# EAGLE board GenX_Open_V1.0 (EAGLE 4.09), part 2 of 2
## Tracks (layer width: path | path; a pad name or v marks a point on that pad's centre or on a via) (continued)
N$29  (via drill 0.43) (continued)
  Top 0.406: 31.55,98.37 v31.77,99.24 | 41.44,102.68 D1.C | v39.12,101.7 39.12,100.97 38.63,100.97 38.51,100.84 38.5,100.85 L3.1 37.55,100.85 36.85,100.15 36.63,100.1 36.83,100.1
  Bottom 0.203: 36.3,100.05 v36.73,100.1
  Bottom 0.406: v31.77,99.24 32.59,100.05 36.3,100.05 | v41.4,102.64 40.06,102.64 v39.12,101.7
N$30
  Top 0.203: R50.1 9.42,105.39 12.83,105.39 13.16,105.69 J15.1
N$31
  Top 0.203: R43.2 26.01,25.38 26.01,24.05 LD2.P$1
N$32
  Top 0.61: J6B.2 32.84,6.15 32.84,6.27
  Top 1.016: U9.5 U9.6 U9.7 U9.8 31.27,11.84 32.82,10.29 32.84,6.27
  Bottom 1.016: J6.4 32.26,9.6 32.79,9.07 32.84,6.15 32.82,6.15 32.84,6.12 J6B.2
N$33
  Top 0.203: LD3.P$1 21.07,23.76 21.27,23.96 R42.2
N$34
  Top 0.203: U8.8 23.88,14.28 | 23.16,14.28 U8.7 22.84,14.3 | 21.79,14.3 U8.6 21.74,14.33 | 20.55,14.33 U8.5
  Top 0.61: 24.46,12.17 24.21,12.42 | 26.19,2.9 26.16,2.92 J4.4
  Top 1.016: 23.88,14.28 23.16,14.28 | 22.84,14.3 21.79,14.3 | 21.74,14.33 20.55,14.33 | 24.21,12.42 U8.8 | 24.46,12.17 27.58,12.14 28.07,11.61 28.07,3.25 27.71,2.9 26.19,2.9
N$35
  Top 0.203: R40.2 25.83,28.52 25.83,28.17 24.51,26.85 24.51,21.21 24.33,21.03 20.5,21.03 20.4,20.93 20.4,19.84 20.42,19.81 20.4,19.79 U8.4
N$36  (via drill 0.43)
  Top 0.203: v23.47,21.87 23.47,25.88 23.32,26.04 v22.53,26.04 | 21.16,28.65 R41.2 | v22.35,28.65 21.16,28.65 | 21.16,28.65 21.11,28.6 | U9.4 v26.24,19.86
  Bottom 0.203: v22.53,26.04 22.53,27.25 22.38,27.41 22.38,28.63 v22.35,28.65 | v23.47,21.87 26.06,21.84 26.16,21.74 26.16,19.94 v26.24,19.86
N$37
  Top 0.406: J12.1 11.81,45.85 11.35,46.31 L1.2
N$38  (via drill 0.43)
  Top 0.203: v29.9,57.89 30.35,58.24 30.35,62.87 29.59,63.7 29.59,64.39 29.36,64.64 28.83,64.64 U7.29 | v32,57.35 32,56.08 31.24,55.32 31.24,54.08 32,53.31 32,49.94 30.61,48.54 30.61,40.16 v31.01,39.78 | C61.1 18.44,20.8 18.69,21.06 19.63,21.06 20.34,21.77 22.35,21.77 22.61,22.02 22.61,23.7 v22.55,23.85
  Bottom 0.203: v29.9,57.89 30.18,57.89 30.63,57.43 31.55,57.43 31.75,57.23 31.77,57.35 v32,57.35 | v31.01,39.78 30.89,39.57 25.81,39.57 25.38,39.14 25.38,38.94 25.43,29.54 25.43,29.39 25.22,29.18 23.75,29.18 23.14,28.07 23.14,27.08 23.5,26.7 23.5,25.45 23.29,25.25 23.29,24.71 22.5,23.93 v22.55,23.85
N$39
  Top 0.254: 35.92,105.49 36.14,105.49 | 35.18,106.22 34.67,106.22 34.44,106.45 | C63.1 32.69,106.7 32.94,106.45
  Top 0.305: 35.18,106.22 35.92,105.49 | 32.94,106.45 34.44,106.45
  Top 0.406: D3.A 38.45,105.16 38.48,105.13 L3.2 36.3,105.05 36.14,105.49 R36.2
N$40
  Top 0.203: R31.2 8.94,18.21 9.98,17.17 10.34,17.17 10.41,17.09 10.46,17.14 U12.2
N$41  (via drill 0.43)
  Top 0.203: R57.1 16.76,40.53 15.75,40.16 15.14,39.34 v14.53,39.34 | U11.1 17.04,35.26 16.23,35.23 15.47,35.23 15.32,35.31 15.32,35.36 15.14,35.51 14.25,35.51 | J9.2 3.91,35.33 4.09,35.51 9.02,35.51 9.35,35.84 12.17,35.84 12.5,35.51 14.25,35.51 | v14.35,36.14 14.35,35.53 14.25,35.51
  Bottom 0.203: v14.53,39.34 14.53,38.51 14.12,38.2 14.12,36.42 v14.35,36.14
N$42
  Top 0.406: U12.6 U12.5 16.1,8.41 15.67,7.98 8.1,7.98 7.82,7.7 J8.3
N$43
  Top 0.406: U12.8 U12.7 14.22,17.14 14.07,16.99 14.07,10.13 13.59,9.63 6.73,9.63 5.28,8.48 J8.4
N$44
  Top 0.203: R48.1 22.48,99.31 22.02,99.62 22.02,103.73 21.89,103.86 20.57,103.86 20.4,104.04 J16.1
N$45
  Top 0.61: D4.C 40.78,10.68 40.16,10.06 38.3,10.06 37.8,9.55 37.8,6.27 37.95,6.12 J6B.1 | J11.1 48.9,6.02 48.95,5.97 48.9,5.92
  Top 1.016: J6B.1 37.92,3.3 38.51,2.72 48.54,2.72 48.9,3.07 48.9,5.92 | J11.1 52.7,6.12 52.98,5.84 52.98,5.08 53.54,4.52 J6C.2
  Bottom 0.61: 37.72,2.9 37.92,3.1 | 37.92,5.44 37.87,5.49 37.87,6.12 J6B.1
  Bottom 1.016: J6.3 23.44,5.56 23.77,5.23 30.12,5.23 30.23,5.13 30.23,3.63 30.96,2.9 37.72,2.9 | 37.92,3.1 37.92,5.44
N$47
  Top 0.203: R46.1 28.32,97.51 27.91,97.81 27.91,104.27 27.46,104.52 J17.1
N$48  (via drill 0.43)
  Top 0.203: v12.98,62.26 12.98,62.31 15.77,62.31 U7.8 | v9.2,62 9.12,62 C41.1 9.37,62.31 9.37,63.32 Q1.1
  Bottom 0.203: v12.98,62.26 12.72,62 v9.2,62
N$49  (via drill 0.43)
  Top 0.203: U11.3 15.28,37.81 v15.14,37.54 | v8.87,20.34 8.18,19.68 2.34,19.68 2.08,19.53 2.08,18.49 2.06,18.47 2.08,18.45 R23.1 | v13.79,29.62 10.03,29.62 v10.01,29.64
  Bottom 0.203: v15.14,37.54 15.14,32.77 13.79,31.24 v13.79,29.62 | v10.01,29.64 10.01,28.6 9.27,27.86 9.12,27.69 8.69,27.25 8.69,26.16 9.32,25.53 9.32,21.01 8.87,20.55 v8.87,20.34
N$51  (via drill 0.43)
  Top 0.203: v12.55,37.74 U11.6 | v11.73,25.68 11.73,23.95 v11.68,23.9 | v11.71,19.46 11.02,19.46 10.9,19.25 6.71,19.25 6.5,19.1 6.5,18.39 6.52,18.37 6.53,18.19 6.52,18.19 R31.1
  Bottom 0.203: v12.55,37.74 13.31,37.72 13.51,37.52 13.51,32.11 13.18,31.83 11.86,31.83 11.63,31.6 11.66,25.76 v11.73,25.68 | v11.68,23.9 11.68,19.43 v11.71,19.46
N$55  (via drill 0.43)
  Top 0.203: R65.2 20.93,85.65 v20.88,85.37 | R45.2 24.44,83.89 24.38,83.95 24.43,84 v24.71,85.75 | R38.2 26.98,84.89 26.95,85.42 | 26.95,85.42 26.95,86.56 26.82,86.79 26.54,87.1 U13.1 | v26.29,84.71 26.95,84.71 26.95,85.42
  Bottom 0.203: v20.88,85.37 24.28,85.37 v24.71,85.75 25.88,85.22 v26.29,84.71
RESET  (via drill 0.43)
  Top 0.203: v14.2,65.35 15.77,65.35 U7.4 | v8.08,65.84 7.95,66.47 v7.95,72.08 7.95,72.92 7.72,73.15 7.72,79.12 8.05,79.45 S1.2 12.47,79.45 12.62,79.22 12.62,77.95 | 12.62,77.95 12.62,75.11 12.88,74.85 12.88,73.74 R5.1 | 12.62,77.95 13.39,77.95 C43.1
  Bottom 0.203: v14.2,65.35 13.31,65.81 v8.08,65.84 | v7.95,72.08 7.29,72.06 J3.5 | S1.1 5.11,79.43 8.51,79.43 S1.2
RESET_A  (via drill 0.43)
  Top 0.203: U4.12 40.1,25.92 39.42,26.57 37.85,26.57 v37.67,26.39 | U3.12 40.02,46.36 38.94,47.3 36.85,47.3 v36.27,47.42 | U1.12 39.92,87.41 39.24,88.06 v36.93,88.06 | U2.12 39.49,66.89 38.81,67.54 35.59,67.54 v35.51,67.46 | v31.8,67.51 31.8,67.54 31.67,67.74 31.47,68.17 31.47,80.92 31.19,81.23 v31.19,88.06 | v23.9,45.64 23.6,46.05 23.6,51.97 22.96,52.55 22.96,55.47 22.71,55.7 20.95,55.7 20.7,55.91 20.7,57.33 U7.15 20.75,58.75 20.75,58.98 19.53,60.38 19.53,61.67 19.74,61.87 23.57,62.2 23.8,62.41 23.8,65.76 v24.13,66.24 | v32.44,47.02 31.34,47.02 31.17,46.81 31.17,41.15 31.98,40.18 31.98,39.01 33.17,37.8 33.17,31.09 32.13,30.4 32.13,27.23 32.41,26.95 v32.41,26.26
  Bottom 0.203: 32.51,47.02 v32.44,47.02 31.98,47.22 30.3,47.22 30.05,46.91 24.05,46.91 23.9,46.81 v23.9,45.64 | 32.51,47.02 32.03,47.27 | v32.41,26.26 32.18,26.44 32.66,26.39 v37.67,26.39 | 32.51,47.02 32.51,47.04 32.74,47.45 v36.27,47.42 | v35.51,67.46 31.95,67.46 31.88,67.54 31.85,67.51 v31.8,67.51 31.85,67.46 31.45,67.46 31.39,67.41 30.38,67.41 29.21,66.24 v24.13,66.24 | v31.19,88.06 31.57,88.01 33.86,87.99 34.14,87.71 36.09,87.71 36.4,88.01 36.83,88.01 v36.93,88.06
RXD0  (via drill 0.43)
  Top 0.203: v16.59,53.57 16.59,52.43 U6.9 | v10.72,53.34 10.08,52.81 9.37,52.81 R26.2 | v13.89,61.44 15.77,61.44 U7.9
  Bottom 0.203: v16.59,53.57 16.38,53.59 11.4,53.59 11.28,53.34 v10.72,53.34 10.29,53.67 9.42,53.67 8,54.69 5.21,54.69 5.03,54.94 5.03,57.99 5.18,58.22 6.3,58.22 6.53,58.45 6.53,60.68 6.73,60.88 10.77,60.88 11.3,61.42 13.31,61.42 v13.89,61.44
RXD1  (via drill 0.43)
  Top 0.203: v15.77,52.65 15.72,52.7 15.72,52.88 15.54,52.96 15.54,54.61 14.63,55.83 14.63,58.47 15.72,59.31 15.82,59.61 15.95,59.77 U7.11 | J2.3 9.68,26.62 v9.7,26.64
  Bottom 0.203: v15.77,52.65 14.99,51.94 14.99,47.9 15.75,47.22 15.75,44.93 16.13,44.55 17.42,44.55 17.68,44.22 17.7,35.23 16.97,34.62 16.97,33.05 17.55,32.51 17.55,30.89 17.91,30.53 17.91,28.57 18.14,28.35 20.3,28.35 20.37,28.32 20.47,28.22 20.47,26.52 20.24,26.26 16.97,26.26 16.28,25.6 16.28,25.3 16.1,25.15 13.31,25.15 13.23,25.09 J1.3 12.52,25.09 12.27,24.84 10.21,24.84 9.98,25.12 9.98,26.62 9.96,26.64 v9.7,26.64
SCK  (via drill 0.43)
  Top 0.203: v5.82,95.99 15.72,95.99 J7.5 | v5.71,80.24 6.02,79.68 6.02,71.4 5.84,71.12 5.84,69.52 | v14.15,69.47 14.15,66.37 14.3,66.22 15.77,66.22 U7.3 | v5.31,60.66 5.41,60.58 5.18,60.35 5.18,58.52 4.85,58.17 4.42,58.01 4.32,57.86 R10.1 | 5.84,69.52 5.84,67.94 6.1,67.67 6.1,64.31 6.07,64.19 v5.74,64.03 | 5.84,69.52 J3.3
  Bottom 0.203: v5.82,95.99 5.71,95.48 5.71,85.52 5.41,85.22 5.41,81.1 5.71,80.8 v5.71,80.24 | v14.15,69.47 13.95,69.52 J3.3 | v5.31,60.66 5.41,60.78 5.74,61.24 v5.74,64.03
SCL  (via drill 0.43)
  Top 0.203: U11.7 12.45,36.5 v12.7,36.47 | v5.69,45.57 5.69,48.79 5.84,48.95 J10.3 | U7.19 23.9,58.98 23.44,59.44 22.63,59.49 v21.36,60.43 | v16.74,58.34 16.74,58.24 17.04,57.78 v17.04,55.24 | v6.68,56.13 5.49,56.13 5.23,56.39 5.23,57.78 5.66,58.22 5.66,59.72 6.25,60.6 6.25,61.19 5.99,61.49 4.75,61.49 4.24,61.82 3.63,61.82 3.63,61.8 J10B.3 | R61.1 33.88,58.14 v32.99,58.14
  Bottom 0.203: v12.7,36.47 3.99,36.47 3.79,36.63 3.79,45.34 3.94,45.57 v5.69,45.57 | J10B.3 4.38,61.81 4.47,61.59 4.47,54.41 4.83,54 6.45,54 6.63,53.82 6.63,49.15 6.93,48.84 | v16.74,58.34 17.83,58.34 17.93,58.42 17.93,60.68 18.14,60.88 20.55,60.88 20.95,60.43 v21.36,60.43 21.36,60.45 21.39,60.48 21.36,60.5 21.36,60.55 22.28,61.87 24.69,61.87 25.81,60.38 25.81,58.95 26.01,58.8 30.48,58.8 30.99,58.14 v32.99,58.14 | v17.04,55.24 16.69,55.32 16.08,54.74 9.68,54.74 8.18,56.06 6.76,56.06 v6.68,56.13 | J10.3 6.93,48.84 | 6.93,48.84 6.96,48.84 6.99,48.82
SDA  (via drill 0.43)
  Top 0.203: U11.5 11.5,39.09 v11.56,39.78 | U7.20 24.7,59.32 24.38,59.64 23.93,59.64 23.01,60.55 22.68,60.55 v22.66,60.63 | R60.1 33.07,56.11 v32.66,55.63 | v11.48,55.6 11.48,54.69 11.76,54.56 11.76,51.92 v11.3,51.56 | v15.8,55.6 15.49,56.26 v15.49,58.04
  Bottom 0.203: v11.56,39.78 11.56,40.72 11.35,40.95 8.36,40.95 8.18,41.17 8.18,46.2 7.92,46.53 4.52,46.53 4.37,46.71 4.37,48.44 | J10B.2 3.52,60.56 3.5,60.58 3.02,60.58 2.52,60.07 2.52,58.24 2.69,58.06 3.45,58.06 3.76,57.76 3.76,54.28 4.37,53.67 J10.2 4.37,48.49 4.39,48.46 4.37,48.44 | v32.66,55.63 31.7,55.63 30.63,56.77 29.87,56.77 28.78,57.56 28.78,58.04 28.55,58.22 25.63,58.22 25.35,58.45 25.35,60.2 24.49,61.42 22.99,61.42 22.63,60.76 22.63,60.6 | 22.63,60.6 v22.66,60.63 | 22.63,60.6 22.63,60.1 22.3,59.59 20.75,59.61 19.58,60.35 18.62,60.38 18.36,60.12 18.36,57.58 18.26,57.4 16.92,57.4 15.98,57.68 v15.49,58.04 | v11.48,55.6 15.72,55.6 15.95,55.73 v15.8,55.6 | v11.3,51.56 8.33,51.56 8.13,51.36 8.1,48.72 7.29,47.62 4.42,47.62 4.39,47.55 4.39,48.41 4.37,48.44
SLEEP  (via drill 0.43)
  Top 0.203: U3.14 41.2,45.36 v40.89,44.76 v40.89,40.62 | U4.14 40.64,24.92 40.08,24.46 | 40.08,24.46 39.65,24.11 R29.1 | U1.14 40.46,86.41 40.18,86.18 40.18,81.64 40.21,81.64 40.23,81.61 40.18,81.56 v40.18,77.8 | U2.14 41.2,65.89 v40.87,65.25 40.62,64.75 40.62,60.55 40.36,60.3 40.36,57.07 40.16,56.87 38.63,56.87 38.46,56.69 38.46,53.87 37.74,53.16 v37.74,50.49 | 40.08,24.46 39.93,24.46 v39.93,24.41 | v38.1,30.07 37.64,30.2 37.64,33.07 38.46,33.58 38.46,37.26 38.58,37.36 v39.98,37.36
  Bottom 0.203: 40.89,40.59 v40.89,40.62 40.89,38.2 v39.98,37.36 | v39.93,24.41 39.24,24.41 38.91,24.74 38.91,29.9 v38.1,30.07 | v40.89,44.76 40.59,44.76 40.16,44.15 38.68,44.15 38,45.01 38,50.24 v37.74,50.49 | v40.87,65.25 40.87,68.43 40.62,68.68 40.62,73.41 39.32,74.52 39.32,77.29 v40.18,77.8
SS  (via drill 0.43)
  Top 0.203: v14.66,92.69 15.72,92.69 J7.2 | v6.53,84.61 6.48,84.56 5.77,84.56 R2.1 | v18.47,74.07 18.47,72.03 18.31,71.68 18.31,70.33 U7.44
  Bottom 0.203: v14.66,92.69 9.58,92.69 9.3,92.41 9.3,86.13 8.99,85.83 6.73,85.83 6.58,85.62 6.58,84.61 v6.53,84.61 6.55,84.3 6.55,83.19 7.95,81.81 10.95,81.81 11.99,80.72 15.42,80.72 15.7,80.49 15.7,74.6 16.1,74.07 v18.47,74.07
STEP_A  (via drill 0.43)
  Top 0.203: U1.16 43.58,84.17 43.18,83.77 43.18,82.98 v42.88,82.68 | U7.36 24.7,70.6 24.46,70.84 24.46,72.52 25.25,73.3 25.25,75.44 24.64,76 24.64,81.61 v24.94,81.79
  Bottom 0.203: v42.88,82.68 35.36,82.68 35.23,82.58 35.23,81.94 34.8,81.51 32.87,81.51 32.21,82.02 25.6,82.02 25.38,81.79 v24.94,81.79
STEP_X  (via drill 0.43)
  Top 0.203: U4.16 43.76,23.05 42.85,22.5 v42.85,21.49 | v26.67,73.53 26.77,73.53 26.9,73.41 26.9,65.71 27.15,65.43 27.43,65.43 U7.30 | v19.28,27.05 22.68,27.05 23.65,27.84 v24.11,27.84 | v9.4,73.15 9.32,73.15 9.3,73.18 9.12,73 v9.12,70.79 | v8.43,47.75 8.43,48.18 8.18,48.44 8.18,49.96 7.98,50.16 v3.2,50.16
  Bottom 0.203: v42.85,21.49 33.25,21.49 33.05,21.69 29.62,21.69 28.5,22.68 25.04,22.68 24.08,23.47 24.08,26.09 v24.11,27.84 | v26.67,73.53 25.07,73.53 24.64,73.28 22.3,73.28 21.84,73.69 20.47,73.69 19.53,72.49 14.86,72.49 14.2,73.15 v9.4,73.15 | v3.2,50.16 3.2,51.1 2.95,51.28 1.22,51.28 1.09,51.41 1.09,70.43 1.32,70.64 8.48,70.64 v9.12,70.79 | v8.43,47.75 8.59,47.75 9.09,47.14 9.09,41.78 9.37,41.5 15.21,41.5 15.42,41.3 15.42,38.73 16,38.15 16,36.96 15.65,36.58 15.65,32.51 14.91,31.5 14.91,28.12 15.04,27.91 16.26,27.91 17.12,27.05 v19.28,27.05
STEP_Y  (via drill 0.43)
  Top 0.203: U3.16 43.68,43.5 42.77,42.95 v42.77,41.94 | U7.35 25.5,68.68 25.83,68.3 25.83,65.18 25.4,64.82 25.4,60.53 26.87,58.8 26.87,55.85 25.68,54.53 25.68,45.09 25.35,44.68 25.35,44.04 26.11,43.28 26.11,40.97 v26.36,40.72
  Bottom 0.203: v26.36,40.72 26.75,40.72 27.25,40.03 29.36,40.03 29.87,40.69 32.89,40.69 33.05,40.82 33.05,41.71 33.3,41.94 v42.77,41.94
STEP_Z  (via drill 0.43)
  Top 0.203: U2.16 43.63,64.02 42.72,63.48 v42.72,62.46 | v22.99,63.22 22.99,64.87 22,66.14 21.77,66.42 20.19,66.42 19.96,66.65 19.96,69.04 U7.42 | v32.13,59.05 32.13,59.36 32.87,59.64 32.87,61.57 32.51,61.82 v32.51,62.41
  Bottom 0.203: v32.51,62.41 32.72,62.46 v42.72,62.46 | v22.99,63.22 22.99,62.41 23.19,62.31 24.89,62.31 26.31,60.58 26.31,59.51 26.54,59.33 30.94,59.33 31.83,59.13 v32.13,59.05
THERM  (via drill 0.43)
  Top 0.203: U7.32 28.83,67.08 29.41,67.08 29.59,67.26 29.59,74.8 28.65,75.62 28.65,76.78 28.35,77.08 C54.1 28.35,77.23 28.32,77.27 28.55,77.5 28.55,78.79 28.88,79.12 v28.88,79.53 28.88,79.96 29.26,80.34 29.26,81 29.29,81.03 R39.2 29.29,81.53 29.29,84.58 R38.1 | v17.3,25.43 17.3,29.97 v16.99,30.1 | v11.12,50.32 12.22,50.32 12.37,50.47 12.37,57.3 11.61,57.73 11.61,59.08 11.79,59.33 13.82,59.33 14.02,59.46 v14.02,59.77 | v19.23,63.7 18.06,64.82 18.06,67.84 17.25,68.68 17.25,74.93 17.7,75.49 v17.7,76.4
  Bottom 0.203: v16.99,30.1 16.99,32.26 16.41,32.77 16.41,34.9 17.09,35.48 17.04,42.32 16.76,42.6 10.82,42.6 10.62,42.88 10.62,46.61 11.51,47.14 11.51,48.92 11.12,49.25 v11.12,50.32 | v14.02,59.77 16.54,59.77 16.59,59.74 16.71,59.87 16.71,62.03 16.92,62.23 19,62.23 19.23,62.46 v19.23,63.7 | v17.7,76.4 17.68,76.68 16.82,77.55 16.82,79.98 17.09,80.19 20.12,80.19 20.52,79.78 26.9,79.78 27.13,79.48 28.83,79.48 v28.88,79.53 | v17.3,25.43 17.3,22.4 16.64,21.74 16.64,3.3 17.04,2.9 18.14,2.9 18.16,2.92 J4.1
THERM2  (via drill 0.43)
  Top 0.203: v26.75,75.62 27.38,75.62 27.51,75.49 27.51,67.84 U7.33 | v19.96,78.97 19.99,79.76 20.14,79.96 20.14,80.34 20.09,80.39 20.12,80.42 R44.2 20.57,80.9 21.59,81.38 | 21.59,81.38 22.25,82.04 R45.1 20.27,83.82 C55.1 | v17.4,21.26 17.4,24.21 18.14,24.66 18.14,25.88 17.86,26.16 17.86,30.25 18.19,30.58 21.34,30.58 21.64,30.84 21.64,39.93 21.46,40.06 21.46,43.23 21.69,43.41 22.35,43.41 22.48,43.54 22.48,47.12 22.68,47.32 22.68,49 v22.28,49.4 | v31.19,50.34 31.19,53.39 30.61,53.98 30.61,55.32 31.19,56.08 31.19,63.27 30.5,64.03 30.5,77.34 v30.12,78.05 | v21.57,81.36 21.59,81.38 | J6.1 17.6,9.58 17.4,9.83 v17.4,12.9
  Bottom 0.203: v26.75,75.62 26.75,77.44 26.42,77.78 23.7,77.78 23.62,77.85 22.38,78.97 v19.96,78.97 | v22.28,49.4 28.83,49.4 29.74,50.34 30.86,50.34 30.91,50.37 v31.19,50.34 | v30.12,78.05 30.12,80.14 29.82,80.49 23.67,80.49 23.06,81.36 v21.57,81.36 | v17.4,12.9 v17.4,21.26
TXD0
  Top 0.203: U6.10 16.54,51.89 16.18,51.89 16.18,51.84 15.16,51.84 14.88,52.05 14.88,54.71 14.02,55.85 14.02,58.67 15.01,59.49 15.01,60.53 15.14,60.63 15.85,60.63 U7.10
TXD1  (via drill 0.43)
  Top 0.203: U7.12 18.26,57.33 18.26,55.07 18.54,54.74 20.85,54 20.9,53.77 20.9,44.02 21.03,43.89 21.03,39.73 21.21,39.45 21.21,31.34 21.16,31.22 20.98,31.04 16.82,31.04 15.57,30.07 J1.2 12.52,26.36 12.29,26.59 11.33,26.59 11.05,26.31 10.54,25.27 10.29,25.02 8.46,25.02 v8.43,25.04 | v4.5,25.04 3.5,25.04 J2.2
  Bottom 0.203: v4.5,25.04 v8.43,25.04
VDD  (via drill 0.43)
  Top 0.203: 33.91,91.64 33.87,91.6 C6.1 | v41.71,85.19 41.92,85.41 | C9.1 38.2,80.49 38.2,80.21 39.24,80.24 39.29,80.19 R8.1 39.16,82.41 39.09,82.63 39.04,82.68 38.66,82.96 38.65,82.97 C8.1 38.65,83.15 38.63,83.16 38.66,83.19 38.66,83.95 38.53,84.07 37.85,84.07 37.68,84.31 37.68,85.08 37.57,85.19 v37.72,85.19 37.69,84.3 33.98,84.32 C7.1 33.63,84.4 32.82,83.59 v32.72,83.59 | 32.77,71.53 32.84,71.55 32.82,71.53 32.75,71.51 C15.1 | v41.96,64.64 42.2,64.89 | 38.71,62.66 38.68,62.64 38.7,62.62 C17.1 38.7,62.45 38.71,62.43 38.91,62.26 38.71,62.18 38.72,60.31 R16.1 39.34,59.66 39.29,59.72 38.23,59.72 37.97,59.97 C18.1 | v35.51,64.67 35.51,64.62 34.69,63.8 C16.1 33.74,63.8 32.69,63.78 v32.08,64.16 | 34.11,30.23 34.09,30.28 34.09,30.15 C33.1 | v41.88,23.7 42.1,23.92 | R29.2 36.72,23.74 36.65,23.67 36.52,23.7 v35.64,23.7 35.64,23.65 34.82,22.83 C34.1 | 38.82,21.65 38.81,21.67 | C35.1 38.82,21.48 38.84,21.46 39.22,21.18 39.27,21.13 39.33,20.92 R32.1 39.47,18.69 39.42,18.75 38.63,18.75 38.38,19 C36.1 | 34.19,51.71 34.01,51.54 34.01,50.6 33.97,50.56 C24.1 | U3.15 42.28,44.36 v42.01,44.15 | 38.76,42.14 38.73,42.11 38.75,42.1 C26.1 38.75,41.92 38.76,41.91 39.14,41.63 39.17,41.66 39.13,41.54 39.13,41.47 39.14,39.34 R24.1 39.4,39.14 39.34,39.19 38.56,39.19 38.05,39.17 C27.1 | C25.1 34.74,43.27 35.56,44.09 v35.94,44.04 | C39.1 17.62,44.52 v16.87,43.69 16.87,43.66 17.64,42.88 C40.1 | 14.36,45.81 14.38,45.82 14.25,45.7 v14.25,44.32 | v24.71,56.59 24.71,56.62 | R35.2 13.05,57.46 v12.52,58.37 | 9.37,59.23 9.35,59.26 | 9.37,59.23 R18.2 | v10.13,58.47 9.37,59.23 | U7.27 28.99,63.03 v29.54,62.48
  Top 0.203: v28.09,83.41 28.13,83.41 | U7.5 15.48,64.63 15.29,64.82 14.81,64.82 14.48,64.49 14.3,64.49 v14.02,64.11 | R58.2 19.86,37.97 v20.17,38.28 | R57.2 20.05,39.64 v20.14,39.32 | v23.47,40.11 23.52,40.06 23.57,40.11 | 0.81,37.19 0.79,37.16
  Top 0.305: 41.92,85.41 U1.15 | 42.2,64.89 U2.15 | 42.1,23.92 U4.15 | v24.05,92.02 23.98,91.92
  Top 0.406: 0.81,37.19 0.81,44.98 | 38.82,21.65 38.8,21.65 38.79,21.64 38.82,21.6 C35.1
  Bottom 0.203: 41.53,64.36 v41.96,64.64 | 24.16,91.72 23.95,92.02 v24.05,92.02 | 37.57,71.25 v37.62,71.3 | 14.33,43.99 v14.25,44.32 | 24.11,60.58 v24.05,60.63 24.31,60.45 | 10.52,58.8 v10.13,58.47 | 32.69,83.59 v32.72,83.59 | 7.9,64.19 7.87,64.21 | v8,64.14 7.9,64.19 | 7.9,64.19 7.98,64.11 | v35.51,64.67 35.66,64.67 | v28.09,83.41 28.04,83.41 27.89,83.57 27.89,83.8
  Bottom 0.305: v37.72,85.19 v41.71,85.19 | v35.51,64.67 36.07,64.26 41.17,64.26 41.53,64.36 | v35.64,23.7 38.84,23.7 39.19,23.34 40.74,23.34 41.1,23.7 v41.88,23.7 | v35.94,44.04 37.49,44.07 38.02,43.48 41.53,43.48 v42.01,44.15 | 27.89,83.8 25.65,83.77 v25.09,83.08 | v26.77,91.29 26.11,91.72 24.16,91.72 | v37.29,65.18 37.29,68.2 37.57,68.48 37.57,71.25 | v32,41.48 28.42,41.48 v27.91,40.87 | v3.66,64.95 7.11,64.95 7.62,64.41 v8,64.14 | v16.87,43.69 15.54,43.69 15.24,43.99 14.33,43.99 | v24.71,56.59 24.71,59.41 24.31,60.45 | 10.52,58.8 12.17,58.8 12.39,58.57 v12.52,58.37 | v29.54,62.48 30.25,62.48 v32.08,64.16 | v28.09,83.41 28.09,83.64 28.5,84.05 31.01,84.05 31.45,83.59 32.69,83.59 | 7.98,64.11 v14.02,64.11
  Bottom 0.406: v20.17,38.28 20.17,34.92 20.24,34.59 S2.5 | v20.14,39.32 23.09,39.34 23.44,39.6 v23.47,40.11 | v37.29,65.18 36.17,65.18 35.66,64.67
  pour Top: 0.18,117.96 60.3,117.96 60.3,110.39 38.3,110.39 38.23,60.22 38.23,16.79 60.22,16.79 60.22,0.13 0.1,0.13
VPP  (via drill 0.43, 0.51, 0.61)
  Top 0.203: C20.1 46.74,53.03 46.56,53.24 46.56,54.05 46.38,54.15 C19.1 | v48.08,44.2 47.75,45.11 48.13,44.65 48.23,44.55 48.54,44.53 | 48.54,44.53 48.21,44.83 47.7,45.39 47.68,45.34 47.9,44.68 47.5,45.31 47.75,44.5 47.3,45.24 47.68,44.07 47.04,45.31 U3.22 | U3.28 47.22,48.36 47.22,48.59 47.65,48.51 47.93,49.05 47.6,48.72 47.45,48.72 | v47.55,49.28 47.45,48.72 | 47.45,48.72 47.14,48.79 47.12,48.82 47.14,49.35 47.07,48.46 47.45,48.72 | v49.05,43.92 48.92,43.94 48.95,43.51 47.95,43.79 48.56,44.32 48.59,44.3 48.92,44.3 49.15,44.32 48.54,44.53 | C29.1 46.82,32.58 46.56,32.79 46.56,33.6 46.46,33.71 C28.1 | U4.28 47.3,27.92 47.3,28.14 47.73,28.07 48.01,28.6 47.68,28.27 47.52,28.27 | v47.62,28.83 47.52,28.27 | 47.52,28.27 47.22,28.35 47.19,28.37 47.22,28.91 47.14,28.02 47.52,28.27 | C2.1 46.64,94.07 46.38,94.28 | v47.98,85.24 47.65,86.16 48.03,85.7 48.13,85.6 48.44,85.57 | 48.44,85.57 48.11,85.88 47.6,86.44 47.57,86.39 47.8,85.72 47.4,86.36 47.65,85.55 47.19,86.28 47.57,85.11 46.94,86.36 U1.22 | U1.28 47.12,89.41 47.12,89.64 47.55,89.56 47.83,90.09 47.5,89.76 47.35,89.76 | v47.45,90.32 47.35,89.76 | 47.35,89.76 47.04,89.84 47.02,89.86 47.04,90.4 46.97,89.51 47.35,89.76 | v48.95,84.96 48.82,84.99 48.84,84.56 47.85,84.84 48.46,85.37 48.49,85.34 48.82,85.34 49.05,85.37 48.44,85.57 | C11.1 46.69,73.55 46.51,73.76 46.51,74.57 46.33,74.68 C10.1 | v48.03,64.72 47.7,65.63 48.08,65.18 48.18,65.08 48.49,65.05 | 48.49,65.05 48.16,65.35 47.65,65.91 47.62,65.86 47.85,65.2 47.45,65.84 47.7,65.02 47.24,65.76 47.62,64.59 46.99,65.83 U2.22 | U2.28 47.17,68.89 47.17,69.11 47.6,69.04 47.88,69.57 47.55,69.24 47.4,69.24
  Top 0.203: v47.5,69.8 47.4,69.24 | 47.4,69.24 47.09,69.32 47.07,69.34 47.09,69.88 47.02,68.99 47.4,69.24 | 48.49,65.05 49.1,64.85 48.87,64.82 48.54,64.82 48.51,64.85 47.9,64.31 48.87,64.08 48.9,64.36 48.87,64.39 48.9,64.41 v48.9,64.47 | 47.17,99.39 C50.1 46.02,98.91 v46,98.88 | 47.17,101.5 D2.C 49.05,102.06 | C51.1 40.66,98.58 | 41.43,100.69 41.43,100.66 | 44.73,95.22 44.63,95.33 v44.63,96.14 44.63,95.99 44.74,95.87 C1.1
  Top 0.254: U4.22 47.73,24.92 48.03,24.61 v49.07,23.52 | U4.28 47.26,27.98 48.28,29.01 v48.74,29.31 48.69,29.34 48.72,29.34 | v47.7,24.33 47.8,23.85 46.86,24.79 46.89,24.79 | 46.89,24.79 47.12,24.79 47.85,24.05 47.85,24.36 47.45,24.77 47.55,24.77 48.16,24.16 48.16,23.5 48.11,23.44 48.74,23.19 49.05,23.93 48.08,24.49 v48.11,23.6 46.89,24.79
  Top 0.305: 46.38,94.28 46.38,95.1 46.28,95.2 C1.1
  Top 0.406: v48.64,49.78 48.77,49.51 47.78,49.05 48.49,50.06 47.42,49.55 v47.55,49.28 | v48.06,52.22 C20.1 48.42,52.8 48.42,52.08 48.41,52.07 49,52.88 48.79,53.09 v48.69,53.09 | C21.1 56.33,52.6 56.34,52.6 | 48.72,29.34 48.84,29.06 47.85,28.6 48.56,29.62 47.5,29.11 v47.62,28.83 | v48.13,31.77 C29.1 48.5,32.35 48.5,31.63 48.49,31.62 49.07,32.44 48.87,32.64 v48.77,32.64 | C30.1 56.41,32.15 56.41,32.16 | v48.54,90.83 48.67,90.55 47.68,90.09 48.39,91.11 47.32,90.6 v47.45,90.32 | v47.95,93.27 C2.1 48.32,93.84 48.32,93.12 48.31,93.12 48.9,93.93 48.69,94.13 v48.59,94.13 | C3.1 56.23,93.65 56.24,93.65 | v48.59,70.31 48.72,70.03 47.73,69.57 48.44,70.59 47.37,70.08 v47.5,69.8 | v48.01,72.75 C11.1 48.37,73.32 48.37,72.6 48.36,72.59 48.95,73.41 48.74,73.61 v48.64,73.61 | C12.1 56.28,73.12 56.29,73.13 | 40.66,98.58 36.7,98.58 35.53,99.75 35.2,100.05 33.1,100.05 31.55,101.24 31.52,101.24 31.52,102.77 U10.8
  Top 0.61: C53.+ 39.85,111.25 40.23,110.97 40.23,100.97 40.54,100.66 41.43,100.66 C51.1 | 47.19,100.69 41.43,100.69
  Top 0.813: C21.1 54.61,52.63 54.66,52.58 54.84,52.76 56.49,52.76 | 56.49,52.76 56.52,52.78 | v56.84,53.09 56.92,53.09 56.92,52.76 56.49,52.76 | C30.1 54.69,32.18 54.74,32.13 54.91,32.31 56.57,32.31 | 56.57,32.31 56.59,32.33 | v56.92,32.64 57,32.64 57,32.31 56.57,32.31 | C3.1 54.51,93.67 54.56,93.62 54.74,93.8 56.39,93.8 | 56.39,93.8 56.41,93.83 | v56.74,94.13 56.82,94.13 56.82,93.8 56.39,93.8 | C12.1 54.56,73.15 54.61,73.1 54.79,73.28 56.44,73.28 | 56.44,73.28 56.46,73.3 | v56.79,73.61 56.87,73.61 56.87,73.28 56.44,73.28
  Top 1.016: 47.17,101.5 47.19,100.69 47.17,99.39 | X1.1 49.05,102.06
  Bottom 0.203: 56.87,73.61 56.67,73.13 v56.79,73.61 | 59.11,73.64 59.11,73.13 59.58,73.17 | 44.5,96.19 44.6,96.11 v44.63,96.14 | 48.72,29.34 48.72,29.36 48.74,29.34 v48.74,29.31 | v48.11,23.6 47.85,31.73 48.82,32.69 59.31,32.69 59.74,32.26 | 59.33,17.07 50.19,17.12 50.09,16.13 | 47.88,10.11 48.67,10.06 48.46,10.34
  Bottom 0.254: 48.01,23.93 47.98,23.9 48.11,24.21 48.03,31.9 48.82,32.69 48.84,32.72 59.69,32.72 59.72,32.69 59.72,17.48 59.31,17.07 | 50.72,17.04 49.84,16.38 | 49.78,11.96 49.76,11.86 49.73,11.86 | 50.09,10.26 47.8,10.19 | v49.07,23.52 48.67,23.42 48.18,24 48.18,28.57 v48.74,29.31
  Bottom 0.305: v46,98.88 45.49,97.18 44.5,96.19
  Bottom 0.406: v48.64,49.78 48.11,49.43 | v47.55,49.28 47.95,49.33 48.06,49.43 | 48.18,28.98 48.72,29.34 | v47.62,28.83 48.03,28.88 48.13,28.98 | v48.54,90.83 48.01,90.47 | v47.45,90.32 47.85,90.37 47.95,90.47 | v48.59,70.31 48.06,69.95 | v47.5,69.8 47.9,69.85 48.01,69.95
  Bottom 0.61: 49.76,11.86 50.14,11.86 | 50.09,10.41 49.58,10.44 49.61,11.71 50.16,11.91 50.09,16.13 | 50.09,16.13 49.86,16.33 | 50.7,17.12 59.26,17.07 59.74,17.55 59.74,31.37 | 59.77,31.24 59.77,32.61 59.74,32.64 | 47.65,10.16 47.68,10.13 | 47.52,10.13 47.65,10.19 50.09,10.26 | 49.91,16.15 49.76,16.15 | 50.09,16.13 49.91,16.15 | 50.09,10.26 48.46,10.34 | 49.91,16.15 50.09,16.2 | 23.39,1.65 J4.3 23.34,2.21 | 12.88,3.1 12.9,3.12 J8.1 | 47.6,10.13 48.16,10.26 50.09,10.26
  Bottom 0.813: 48.11,49.43 v48.08,44.2 | v48.06,52.22 48.06,49.43 | 48.79,53.09 v48.69,53.09 | v47.7,24.33 48.18,28.98 | 48.13,28.98 v48.13,31.77 | 48.01,90.47 v47.98,85.24 | v47.95,93.27 47.95,90.47 | 48.06,69.95 v48.03,64.72 | v48.01,72.75 48.01,69.95 | v56.92,32.64 56.92,32.61 57.12,32.38
  Bottom 1.016: 55.42,102.03 55.32,102.06 X1.1 | 59.51,94.18 59.49,94.16 | 59.11,73.64 59.46,73.64 59.51,73.58 | 57.02,32.69 59.49,32.69 59.54,32.64 59.54,32.56 59.61,32.49 59.61,32.54 | 57.02,32.69 57,32.66 57,32.64 v56.92,32.64 | 57.02,32.69 57.05,32.72 | v56.84,53.09 56.82,53.11 | 56.84,73.58 56.87,73.61 56.84,73.64 56.84,73.58 | 56.84,73.58 56.82,73.56 | 56.87,94.16 56.84,94.13 | 56.84,94.13 56.82,94.13 56.82,94.11 56.84,94.13 | v48.9,64.47 48.9,57.38 47.75,56.24 47.75,54.56 47.95,54.36 47.95,53.95 48.79,53.11 48.79,53.09 | 49.86,16.33 50.7,17.12 | 59.31,17.07 50.72,17.04 | 49.84,16.38 49.78,11.96 | 59.74,32.26 59.74,17.48 59.33,17.07 | J6C.1 52.86,7.06 52.43,7.49 52.43,9.86 52.12,10.16 48.13,10.16 | 48.13,10.16 47.65,10.16 | 48.13,10.16 47.68,10.13 | 47.65,10.19 48.13,10.16 | 50.09,10.26 50.09,10.41 50.09,16.13 50.09,16.2 | 23.39,1.65 22.81,1.07 13.39,1.07 12.88,1.57 12.88,3.1 | 23.34,2.21 23.37,0.91 45.87,0.91 46.46,1.5 46.46,8.99 47.6,10.13
  Bottom 1.27: 48.79,53.09 v56.84,53.09 | v48.77,32.64 v56.92,32.64 59.74,32.64 | v48.59,94.13 54.99,94.13 | 54.99,94.13 v56.74,94.13 | v56.79,73.61 v48.64,73.61 | 59.56,101.58 59.58,73.17 59.61,32.54 | 59.56,101.58 58.9,102.06 55.32,102.06 | 59.11,73.64 56.84,73.64 | 56.82,53.11 59.49,53.11 | 59.49,94.16 56.87,94.16 | 59.56,101.58 59.51,101.58 59.51,94.18 | 54.99,94.13 54.99,32.87 | 54.99,94.13 54.79,94.11 | 54.79,94.11 54.53,94.11 54.79,94.1 | 54.79,94.1 | 54.79,94.11 54.79,94.1

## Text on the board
tPlace: X | G | Y | G | Z | G | G | G | e | LX | LY | LZ | A | VDD | VDD | VDD | GND | G | G | G | VF | VF | VF | Limit | VPP | Extd | A | RESET | ISP | Z | Y | X | RB | GND | VPP | Bed H | GenX | R1.0 | Extr H | Fan PWM | F1 | F2 | AD | V+ | G | T | G | V+ | R
bPlace: OPEN HARDWARE | GENx | V1.00
Measures: 0.000 | 0.003 | 0.179 | 2.181 | 2.378 | 4.648 | 4.501 | 0.501 | 0.000 | 0.000 | 0.000 | 0.000 | 0.000 | 0.181 | 2.182 | 2.375
_tplace: X | G | Y | G | Z | G | G | G | J19 | A | R52 | J18 | e | R53 | LX | LY | LZ | VDD | VDD | C52 | C60 | VDD | C59 | D2 | GND | D3 | TT | C53 | R51 | G | G | G | D1 | VF | C63 | R36 | VF | VF | C56 | R50 | J15 | J16 | J17 | Limit | R37 | C58 | J7 | C57 | R47 | L3 | C51 | C50 | R48 | X1 | U10 | C2 | VPP | R49 | R46 | R1 | C4 | C3 | C37 | U13 | C70 | C6 | C1 | R3 | J22 | C5 | U1 | R56 | R4 | R2 | C71 | Extd | A | L2 | R45 | C8 | R65 | R6 | C55 | R38 | C7 | S1 | C38 | R8 | R39 | C9 | R44 | R7 | C12 | C43 | R9 | C11 | C46 | C54 | C10 | RESET | C15 | C14 | ISP | J3 | U7 | C13 | R11 | J23 | C42 | R5 | U2 | Q1 | Z | J10B | R12 | R14 | C16 | C17 | C41 | R16 | R13 | C18 | R18 | R10 | R21 | R61 | R15 | C20 | C21 | R60 | R17 | C22 | R35 | U6 | LD4 | C48 | R26 | C24 | C23 | C19 | LD1 | C44 | R19 | J21 | J10 | U3 | C39 | C49 | J5 | Y | R34 | J12 | C40 | C47 | L1 | R20 | R22 | R57 | C25 | C26 | R33 | R24 | R58 | C27 | C30 | R55 | C29 | U11 | R25 | C31 | J1 | S2 | J9 | C45 | C62 | C32 | R59 | C33 | C28 | J20 | U4 | R27 | R40 | R41 | R43 | R28 | R29 | X | R42 | LD3 | C35 | R30 | J2 | LD2 | C34 | C36 | R32 | C61 | 8 | R54 | R23 | R31 | 8 | 8 | U9 | D4 | U8 | U12 | RB | GND | VPP | J6 | Bed H | GenX | Designed and Manufactured by | SOC Robotics, Inc. | R1.0 | J8 | Extr H | Fan PWM | J4 | J6B | J11 | F1 | F2 | AD | V+ | J6C | G | T | G | V+ | R
_bplace: SJ1 | OPEN HARDWARE | SJ100 | GENx | V1.00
